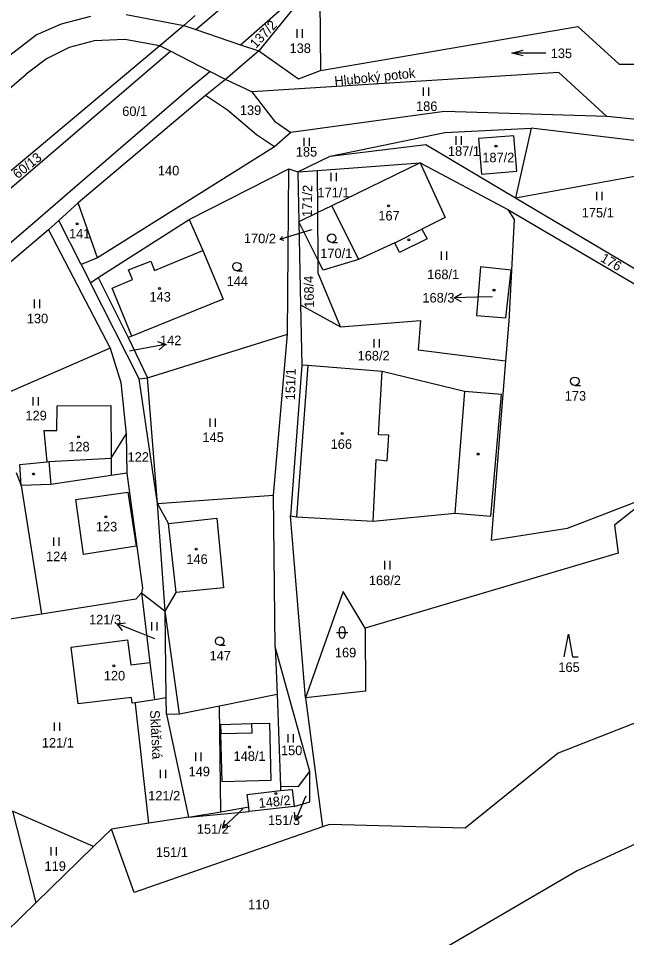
# Model space of a CAD drawing. Extents: x -670359 to -668019, y -978807 to -976674.
# Drawn here: x -669999.1 to -669891.1, y -977284.7 to -977121.4 of the extents above; entities that cross this region are included whole.
import ezdxf

# ---------------------------------------------------------------- set-up
doc = ezdxf.new("R2010")
doc.units = 0
for name, color, linetype in [('Hranice kat_území', 7, 'Continuous'), ('Hranice parcel', 7, 'Continuous'), ('Parcelní čísla', 7, 'Continuous'), ('Pop  PČ popisy', 7, 'Continuous'), ('Vnitřní kresba', 7, 'Continuous'), ('Značky budov', 7, 'Continuous'), ('Značky kultur', 7, 'Continuous')]:
    doc.layers.add(name, color=color, linetype=linetype)

msp = doc.modelspace()

# ---------------------------------------------------------------- linework, layer by layer
at = {"layer": 'Hranice kat_území'}
for points in [[(-669945.6, -977118.07), (-669945.45, -977130.61)], [(-669945.45, -977130.61), (-669899.75, -977122.83)], [(-669899.75, -977122.83), (-669892.44, -977129.5)], [(-669892.44, -977129.5), (-669889.16, -977129.48)]]:
    msp.add_lwpolyline(points, dxfattribs=at)
at = {"layer": 'Hranice parcel'}
for p, q in [((-669917.06, -977165.52), (-669917.76, -977174.17)), ((-669911.59, -977166.08), (-669917.06, -977165.52)), ((-669912.54, -977174.58), (-669911.59, -977166.08)), ((-669917.76, -977174.17), (-669912.54, -977174.58))]:
    msp.add_line(p, q, dxfattribs=at)
for points in [[(-669967.58, -977123.35), (-669935.98, -977096.52)], [(-669959.66, -977126.05), (-669945.23, -977113.35)], [(-669945.23, -977113.35), (-669956.43, -977127.16)], [(-669991.49, -977122.33), (-669986.23, -977120.98)], [(-669979.99, -977120.67), (-669969.73, -977122.61)], [(-669969.73, -977122.61), (-669967.72, -977120.86)], [(-669995.94, -977124.31), (-669991.49, -977122.33)], [(-669969.73, -977122.61), (-669974.03, -977126.23)], [(-669969.73, -977122.61), (-669967.58, -977123.35)], [(-669967.58, -977123.35), (-669959.66, -977126.05)], [(-670000.63, -977127.93), (-669995.94, -977124.31)], [(-669974.03, -977126.23), (-670006.9, -977153.84)], [(-669990.1, -977126.56), (-669994.12, -977128.57)], [(-669985.64, -977125.36), (-669990.1, -977126.56)], [(-669980.2, -977125.14), (-669985.64, -977125.36)], [(-669974.03, -977126.23), (-669980.2, -977125.14)], [(-669972.1, -977127.22), (-669974.03, -977126.23)], [(-669959.66, -977126.05), (-669956.43, -977127.16)], [(-670035.46, -977181.47), (-670011.48, -977160.92), (-669972.1, -977127.22)], [(-669965.11, -977130.8), (-669972.1, -977127.22)], [(-669956.43, -977127.16), (-669949.36, -977132.08)], [(-669994.12, -977128.57), (-669997.72, -977131.3)], [(-670104.59, -977250.52), (-670079.48, -977228.88), (-670031.98, -977188.17), (-670021.47, -977179.22), (-669995.68, -977157.04), (-669989.1, -977151.37), (-669968.95, -977134.02), (-669965.11, -977130.8)], [(-670045.65, -977172.49), (-669997.72, -977131.3)], [(-669962.32, -977132.23), (-669965.11, -977130.8)], [(-669903.15, -977131), (-669957.67, -977134.44)], [(-669949.36, -977132.08), (-669945.45, -977130.61)], [(-669894.63, -977138.78), (-669903.15, -977131)], [(-669962.32, -977132.23), (-669965.9, -977135.05)], [(-669957.67, -977134.44), (-669962.32, -977132.23)], [(-669957.67, -977134.44), (-669953.64, -977139.61)], [(-669965.9, -977135.05), (-669988.51, -977154.12)], [(-669961.97, -977137.67), (-669965.9, -977135.05)], [(-669956.83, -977142.03), (-669961.97, -977137.67)], [(-669923.42, -977137.91), (-669950.75, -977141.67)], [(-669894.63, -977138.78), (-669923.42, -977137.91)], [(-669953.64, -977139.61), (-669950.75, -977141.67)], [(-669888.79, -977139.39), (-669894.63, -977138.78)], [(-669923.4, -977141.67), (-669908.05, -977140.86)], [(-669908.05, -977140.86), (-669910.86, -977153.26)], [(-669889.81, -977143.07), (-669908.05, -977140.86)], [(-669953.62, -977144.17), (-669956.83, -977142.03)], [(-669950.75, -977141.67), (-669953.62, -977144.17)], [(-669943.77, -977145.87), (-669923.4, -977141.67)], [(-669911.11, -977142.21), (-669917.4, -977142.73)], [(-669917.4, -977142.73), (-669916.9, -977149.02)], [(-669910.61, -977148.52), (-669911.11, -977142.21)], [(-669953.62, -977144.17), (-669985.1, -977163.93)], [(-669943.77, -977145.87), (-669926.75, -977143.77)], [(-669926.75, -977143.77), (-669910.86, -977153.26)], [(-669949.51, -977148.63), (-669943.77, -977145.87)], [(-669945.99, -977148.37), (-669927.77, -977147.05)], [(-669927.77, -977147.05), (-669943.48, -977154.66)], [(-669927.77, -977147.05), (-669912.21, -977155.35)], [(-669927.77, -977147.05), (-669923.32, -977156.77)], [(-669968.82, -977157.12), (-669951.12, -977148.07)], [(-669951.36, -977177.48), (-669951.12, -977148.07)], [(-669951.12, -977148.07), (-669949.51, -977148.63)], [(-669949.51, -977148.63), (-669945.99, -977148.37)], [(-669949.51, -977148.63), (-669949.32, -977157.49)], [(-669945.92, -977155.84), (-669945.99, -977148.37)], [(-669916.9, -977149.02), (-669910.61, -977148.52)], [(-669988.51, -977154.12), (-669991.93, -977157.26)], [(-669985.1, -977163.93), (-669988.51, -977154.12)], [(-669910.86, -977153.26), (-669880.3, -977171.38)], [(-669945.92, -977155.84), (-669949.32, -977157.49)], [(-669943.48, -977154.66), (-669945.92, -977155.84)], [(-669945.87, -977164.39), (-669945.92, -977155.84)], [(-669943.48, -977154.66), (-669938.71, -977164.22)], [(-669912.21, -977155.35), (-669880.68, -977173.86)], [(-669912.21, -977155.35), (-669911.08, -977157.1)], [(-669991.93, -977157.26), (-669993.77, -977158.95)], [(-669987.97, -977165.07), (-669991.93, -977157.26)], [(-669984.94, -977167.41), (-669968.82, -977157.12)], [(-669968.82, -977157.12), (-669966.34, -977162.58)], [(-669945.87, -977164.39), (-669949.32, -977157.49)], [(-669949.32, -977157.49), (-669949, -977172.24)], [(-669923.32, -977156.77), (-669927.47, -977158.8)], [(-669911.08, -977157.1), (-669912.02, -977175.17)], [(-669993.77, -977158.95), (-670006.42, -977169.66)], [(-669993.77, -977158.95), (-669982.85, -977179.94)], [(-669927.47, -977158.8), (-669926.5, -977160.55)], [(-669926.5, -977160.55), (-669931.44, -977162.98)], [(-669966.34, -977162.58), (-669962.75, -977171.23)], [(-669932.25, -977161.22), (-669938.71, -977164.22)], [(-669931.44, -977162.98), (-669932.25, -977161.22)], [(-669985.1, -977163.93), (-669987.97, -977165.07)], [(-669938.71, -977164.22), (-669945.02, -977166.09)], [(-669987.97, -977165.07), (-669986.3, -977168.37)], [(-669945.02, -977166.09), (-669945.87, -977164.39)], [(-669941.9, -977176.15), (-669945.86, -977166.62), (-669945.87, -977164.39)], [(-669986.3, -977168.37), (-669984.94, -977167.41)], [(-669984.94, -977167.41), (-669979.64, -977178.07)], [(-669977.7, -977185.39), (-669986.3, -977168.37)], [(-669962.75, -977171.23), (-669978.99, -977177.81)], [(-669949, -977172.24), (-669948.77, -977182.97)], [(-669949, -977172.24), (-669941.9, -977176.15)], [(-669941.9, -977176.15), (-669927.7, -977175.07), (-669928.11, -977180.28), (-669912.59, -977182.2)], [(-669912.02, -977175.17), (-669912.59, -977182.2)], [(-669978.99, -977177.81), (-669979.64, -977178.07)], [(-669979.64, -977178.07), (-669976.19, -977185.22)], [(-669976.19, -977185.22), (-669951.36, -977177.48)], [(-669953.8, -977206.06), (-669951.36, -977177.48)], [(-669982.85, -977179.94), (-670002.6, -977188.53)], [(-669982.85, -977179.94), (-669980.9, -977186.05)], [(-669948.77, -977182.97), (-669950.8, -977209.75)], [(-669947.73, -977183.05), (-669948.77, -977182.97)], [(-669934.53, -977184.09), (-669947.73, -977183.05)], [(-669912.59, -977182.2), (-669915.17, -977214.1)], [(-669977.7, -977185.39), (-669976.19, -977185.22)], [(-669974.43, -977207.58), (-669977.7, -977185.39)], [(-669919.87, -977187.68), (-669934.53, -977184.09)], [(-669980.9, -977186.05), (-669979.97, -977195.23)], [(-669913.31, -977188.2), (-669919.87, -977187.68)], [(-669915.2, -977209.79), (-669913.31, -977188.2)], [(-669992.29, -977194.58), (-669992.23, -977190.19)], [(-669992.23, -977190.19), (-669982.72, -977190.13)], [(-669982.72, -977190.13), (-669982.67, -977199.48)], [(-669994.53, -977194.6), (-669992.29, -977194.58)], [(-669994, -977200.14), (-669994.53, -977194.6)], [(-669979.97, -977195.23), (-669979.85, -977202.18)], [(-669998.89, -977200.62), (-669994, -977200.14)], [(-669982.67, -977199.48), (-669982.65, -977202.6)], [(-669998.63, -977204.37), (-669998.89, -977200.62)], [(-669999.53, -977202.06), (-669998.63, -977204.37)], [(-669982.65, -977202.6), (-669993.36, -977204.18)], [(-669979.85, -977202.18), (-669982.65, -977202.6)], [(-669979.85, -977202.18), (-669977.1, -977222.62)], [(-669993.36, -977204.18), (-669998.63, -977204.37)], [(-669998.63, -977204.37), (-669994.99, -977227.2)], [(-669988.94, -977206.87), (-669979.68, -977205.54)], [(-669979.68, -977205.54), (-669978.18, -977215.12)], [(-669974.43, -977207.58), (-669953.8, -977206.06)], [(-669953.54, -977233.03), (-669953.8, -977206.06)], [(-669901.59, -977211.94), (-669886.67, -977206.18)], [(-669886.67, -977206.18), (-669893.28, -977211.41)], [(-669987.53, -977216.61), (-669988.94, -977206.87)], [(-669973.08, -977226.71), (-669974.43, -977207.58)], [(-669950.8, -977209.75), (-669949.74, -977209.91)], [(-669948.13, -977242.11), (-669950.8, -977209.75)], [(-669949.74, -977209.91), (-669936.14, -977210.71)], [(-669936.14, -977210.71), (-669921.6, -977209.27)], [(-669921.6, -977209.27), (-669915.2, -977209.79)], [(-669972.45, -977211.09), (-669963.9, -977210.16)], [(-669971.1, -977223.39), (-669972.45, -977211.09)], [(-669963.9, -977210.16), (-669962.71, -977222.54)], [(-669893.28, -977211.41), (-669892.61, -977216.37)], [(-669915.17, -977214.1), (-669901.59, -977211.94)], [(-669978.18, -977215.12), (-669987.53, -977216.61)], [(-669892.61, -977216.37), (-669937.56, -977229.74)], [(-669977.1, -977222.62), (-669977.27, -977223.41)], [(-669962.71, -977222.54), (-669971.1, -977223.39)], [(-669978.29, -977224.55), (-669994.99, -977227.2)], [(-669977.27, -977223.41), (-669978.29, -977224.55)], [(-669977.27, -977223.41), (-669975.76, -977235.81)], [(-669977.27, -977223.41), (-669973.08, -977226.71)], [(-669941.43, -977223.21), (-669948.13, -977242.11)], [(-669937.56, -977229.74), (-669941.43, -977223.21)], [(-669994.99, -977227.2), (-670002.18, -977228.33)], [(-669972.86, -977242.12), (-669973.08, -977226.71)], [(-669937.56, -977229.74), (-669937.5, -977240.93)], [(-669989.74, -977233.11), (-669979.73, -977231.81)], [(-669979.73, -977231.81), (-669979.14, -977236.24)], [(-669988.49, -977243.13), (-669989.74, -977233.11)], [(-669947.38, -977255.2), (-669953.54, -977233.03)], [(-669953.54, -977233.03), (-669953.17, -977241.42)], [(-669979.14, -977236.24), (-669975.76, -977235.81)], [(-669975.76, -977235.81), (-669974.94, -977242.47)], [(-669937.5, -977240.93), (-669948.13, -977242.11)], [(-669979.02, -977242.01), (-669988.49, -977243.13)], [(-669978.91, -977243.05), (-669979.02, -977242.01)], [(-669974.94, -977242.47), (-669978.38, -977242.97)], [(-669972.86, -977242.12), (-669974.94, -977242.47)], [(-669972.82, -977244.97), (-669972.86, -977242.12)], [(-669963.43, -977243.51), (-669953.17, -977241.42)], [(-669953.17, -977241.42), (-669952.6, -977257.8)], [(-669948.13, -977242.11), (-669945.09, -977265.04)], [(-669978.38, -977242.97), (-669978.91, -977243.05)], [(-669975.96, -977264.38), (-669978.35, -977243.14), (-669978.38, -977242.97)], [(-669970.51, -977244.96), (-669963.43, -977243.51)], [(-669963.18, -977262.32), (-669963.43, -977243.51)], [(-669879.68, -977242.68), (-669903.28, -977251.92)], [(-669972.82, -977244.97), (-669970.51, -977244.96)], [(-669972.82, -977244.97), (-669968.89, -977263.29)], [(-669903.28, -977251.92), (-669919.77, -977265.25)], [(-669949.4, -977257.86), (-669947.38, -977255.2)], [(-669947.34, -977260.59), (-669947.38, -977255.2)], [(-669958.49, -977259.24), (-669952.58, -977258.58)], [(-669952.6, -977257.8), (-669949.4, -977257.86)], [(-669952.6, -977257.8), (-669952.58, -977258.58)], [(-669952.58, -977258.58), (-669950.52, -977258.35)], [(-669950.52, -977258.35), (-669950.17, -977261.42)], [(-669958.21, -977261.47), (-669958.49, -977259.24)], [(-669950.17, -977261.42), (-669947.34, -977260.59)], [(-669873.27, -977260.54), (-669899.87, -977272.82)], [(-669963.18, -977262.32), (-669958.21, -977261.47)], [(-669958.11, -977262.31), (-669958.21, -977261.47)], [(-669950.17, -977261.42), (-669958.11, -977262.31)], [(-669985.76, -977268.51), (-670000.16, -977262.24)], [(-670000.16, -977262.24), (-669996.01, -977278.51)], [(-669968.89, -977263.29), (-669975.96, -977264.38)], [(-669968.89, -977263.29), (-669958.11, -977262.31)], [(-669968.89, -977263.29), (-669963.18, -977262.32)], [(-669982.59, -977265.41), (-669985.76, -977268.51)], [(-669975.96, -977264.38), (-669982.59, -977265.41)], [(-669978.55, -977276.66), (-669982.59, -977265.41)], [(-669945.09, -977265.04), (-669978.55, -977276.66)], [(-669943.86, -977264.62), (-669945.09, -977265.04)], [(-669919.77, -977265.25), (-669943.86, -977264.62)], [(-669985.76, -977268.51), (-669996.01, -977278.51)], [(-669899.87, -977272.82), (-669928.04, -977289.3)], [(-669996.01, -977278.51), (-670001.38, -977283.75)]]:
    msp.add_lwpolyline(points, dxfattribs=at)
at = {"layer": 'Parcelní čísla'}
for p, q in [((-669947.09, -977158.94), (-669950.79, -977160.09)), ((-669950.79, -977160.09), (-669952.7, -977160.68)), ((-669952.7, -977160.68), (-669952.19, -977160.13)), ((-669951.97, -977160.85), (-669952.7, -977160.68)), ((-669920.41, -977171.73), (-669921.73, -977171.01)), ((-669915, -977170.86), (-669917.73, -977170.92)), ((-669974.4, -977178.75), (-669972.99, -977179.25)), ((-669979.38, -977180.43), (-669976.92, -977179.98)), ((-669980.63, -977230.13), (-669981.56, -977228.95)), ((-669974.9, -977231.63), (-669977.85, -977230.44)), ((-669948.07, -977259.58), (-669948.35, -977260.24)), ((-669959.3, -977261.89), (-669959.97, -977262.51)), ((-669948.73, -977263.02), (-669949.93, -977263.91)), ((-669961.44, -977264.9), (-669962.9, -977265.23))]:
    msp.add_line(p, q, dxfattribs=at)
for points in [[(-669917.73, -977170.92), (-669921.73, -977171.01), (-669920.45, -977170.23)], [(-669976.92, -977179.98), (-669972.99, -977179.25), (-669974.13, -977180.23)], [(-669977.85, -977230.44), (-669981.56, -977228.95), (-669980.07, -977228.74)], [(-669948.35, -977260.24), (-669949.93, -977263.91), (-669950.11, -977262.42)], [(-669959.97, -977262.51), (-669962.9, -977265.23), (-669962.46, -977263.8)]]:
    msp.add_lwpolyline(points, dxfattribs=at)
at = {"layer": 'Vnitřní kresba'}
for points in [[(-669956.43, -977127.16), (-669962.32, -977132.23)], [(-669910.86, -977153.26), (-669882.82, -977148.14)], [(-669932.25, -977161.22), (-669927.47, -977158.8)], [(-669974.95, -977166.16), (-669966.34, -977162.58)], [(-669979.57, -977166.07), (-669975.61, -977164.49)], [(-669975.61, -977164.49), (-669974.95, -977166.16)], [(-669978.85, -977167.79), (-669979.57, -977166.07)], [(-669982.47, -977169.3), (-669978.85, -977167.79)], [(-669978.99, -977177.81), (-669982.47, -977169.3)], [(-669947.73, -977183.05), (-669949.74, -977209.91)], [(-669974.43, -977207.58), (-669976.19, -977185.22)], [(-669935.19, -977195.36), (-669934.53, -977184.09)], [(-669919.87, -977187.68), (-669921.6, -977209.27)], [(-669982.67, -977199.48), (-669979.97, -977195.23)], [(-669933.35, -977195.43), (-669935.19, -977195.36)], [(-669933.64, -977199.99), (-669933.35, -977195.43)], [(-669994, -977200.14), (-669993.7, -977200.11)], [(-669993.7, -977200.11), (-669982.67, -977199.48)], [(-669993.7, -977200.11), (-669993.36, -977204.18)], [(-669936.14, -977210.71), (-669935.56, -977199.76)], [(-669935.56, -977199.76), (-669933.64, -977199.99)], [(-669972.45, -977211.09), (-669974.43, -977207.58)], [(-669973.08, -977226.71), (-669971.1, -977223.39)], [(-669970.51, -977244.96), (-669973.08, -977226.71)], [(-669963.21, -977246.84), (-669957.66, -977246.68)], [(-669963.21, -977246.84), (-669963.17, -977248.43)], [(-669957.66, -977246.68), (-669954.51, -977246.59)], [(-669957.61, -977248.33), (-669957.66, -977246.68)], [(-669954.51, -977246.59), (-669954.3, -977256.78)], [(-669963.17, -977248.43), (-669957.61, -977248.33)], [(-669962.96, -977256.99), (-669963.17, -977248.43)], [(-669954.3, -977256.78), (-669962.96, -977256.99)]]:
    msp.add_lwpolyline(points, dxfattribs=at)
at = {"layer": 'Značky budov'}
for centre in [(-669914.3, -977144.06), (-669933.41, -977154.67), (-669988.67, -977157.87), (-669974.08, -977169.34), (-669914.66, -977169.67), (-669941.62, -977195.11), (-669988.47, -977195.71), (-669983.57, -977209.93), (-669967.54, -977215.69), (-669982.16, -977236.41), (-669958.06, -977250.83), (-669953.38, -977259.09)]:
    msp.add_circle(centre, 0.175, dxfattribs=at)
at = {"layer": 'Značky kultur'}
for p, q in [((-669949.68, -977123.31), (-669949.68, -977124.81)), ((-669948.68, -977124.81), (-669948.68, -977123.31)), ((-669905.47, -977127.53), (-669911.47, -977127.53)), ((-669927.25, -977133.62), (-669927.25, -977135.12)), ((-669926.25, -977135.12), (-669926.25, -977133.62)), ((-669948.42, -977142.58), (-669948.42, -977144.08)), ((-669947.42, -977144.08), (-669947.42, -977142.58)), ((-669921.44, -977142.31), (-669921.44, -977143.81)), ((-669920.44, -977143.81), (-669920.44, -977142.31)), ((-669943.65, -977148.8), (-669943.65, -977150.3)), ((-669942.65, -977150.3), (-669942.65, -977148.8)), ((-669896.45, -977152.16), (-669896.45, -977153.66)), ((-669895.45, -977153.66), (-669895.45, -977152.16)), ((-669943.47, -977161.16), (-669942.47, -977161.16)), ((-669924.03, -977162.78), (-669924.03, -977164.28)), ((-669923.03, -977164.28), (-669923.03, -977162.78)), ((-669960.31, -977166.22), (-669959.31, -977166.22)), ((-669996.33, -977171.34), (-669996.33, -977172.84)), ((-669995.33, -977172.84), (-669995.33, -977171.34)), ((-669935.97, -977178.35), (-669935.97, -977179.85)), ((-669934.97, -977179.85), (-669934.97, -977178.35)), ((-669900.31, -977186.59), (-669899.31, -977186.59)), ((-669996.55, -977188.66), (-669996.55, -977190.16)), ((-669995.55, -977190.16), (-669995.55, -977188.66)), ((-669965.14, -977192.44), (-669965.14, -977193.94)), ((-669964.14, -977193.94), (-669964.14, -977192.44)), ((-669992.89, -977213.61), (-669992.89, -977215.11)), ((-669991.89, -977215.11), (-669991.89, -977213.61)), ((-669934.09, -977217.76), (-669934.09, -977219.26)), ((-669933.09, -977219.26), (-669933.09, -977217.76)), ((-669975.49, -977228.64), (-669975.49, -977230.14)), ((-669974.49, -977230.14), (-669974.49, -977228.64)), ((-669942.64, -977230.48), (-669940.64, -977230.48)), ((-669942.14, -977229.98), (-669942.14, -977230.98)), ((-669941.14, -977229.98), (-669941.14, -977230.98)), ((-669963.38, -977232.75), (-669962.38, -977232.75)), ((-669992.78, -977246.45), (-669992.78, -977247.95)), ((-669991.78, -977247.95), (-669991.78, -977246.45)), ((-669951.26, -977248.55), (-669951.26, -977250.05)), ((-669950.26, -977250.05), (-669950.26, -977248.55)), ((-669967.65, -977251.83), (-669967.65, -977253.33)), ((-669966.65, -977253.33), (-669966.65, -977251.83)), ((-669973.93, -977254.86), (-669973.93, -977256.36)), ((-669972.93, -977256.36), (-669972.93, -977254.86)), ((-669993.37, -977268.63), (-669993.37, -977270.13)), ((-669992.37, -977270.13), (-669992.37, -977268.63))]:
    msp.add_line(p, q, dxfattribs=at)
for points in [[(-669909.47, -977128.03), (-669911.47, -977127.53), (-669909.47, -977127.03)], [(-669902.19, -977234.8), (-669901.44, -977230.8), (-669900.69, -977234.8), (-669899.69, -977234.8)]]:
    msp.add_lwpolyline(points, dxfattribs=at)
for centre, radius in [((-669914.3, -977144.06), 0.175), ((-669933.41, -977154.67), 0.175), ((-669988.67, -977157.87), 0.175), ((-669943.47, -977160.41), 0.75), ((-669929.79, -977160.72), 0.175), ((-669960.31, -977165.47), 0.75), ((-669974.08, -977169.34), 0.175), ((-669914.66, -977169.67), 0.175), ((-669900.31, -977185.84), 0.75), ((-669941.62, -977195.11), 0.175), ((-669988.47, -977195.71), 0.175), ((-669917.46, -977198.77), 0.175), ((-669996.46, -977202.32), 0.175), ((-669983.57, -977209.93), 0.175), ((-669967.54, -977215.69), 0.175), ((-669963.38, -977232), 0.75), ((-669982.16, -977236.41), 0.175), ((-669958.06, -977250.83), 0.175), ((-669953.38, -977259.09), 0.175)]:
    msp.add_circle(centre, radius, dxfattribs=at)
for centre, start, end in [((-669941.64, -977229.98), 0, 180), ((-669941.64, -977230.98), 180, 0)]:
    msp.add_arc(centre, 0.5, start, end, dxfattribs=at)

# ---------------------------------------------------------------- texts
at = {"layer": 'Parcelní čísla'}
for s, rotation, p in [('137/2', 46.8624, (-669956.95, -977126.82)), ('60/13', 38.9704, (-669999.24, -977149.96)), ('171/2', 89.2669, (-669947.01, -977156.65)), ('170/2', 359.1689, (-669959.08, -977161.27)), ('176', 329.8265, (-669895.9, -977164.44)), ('168/4', 91.043, (-669946.62, -977172.77)), ('151/1', 88.4579, (-669950.01, -977189.25)), ('148/2', 5.9314, (-669956.36, -977261.67))]:
    msp.add_text(s, height=1.7, rotation=rotation, dxfattribs=at).set_placement(p)
for s, height, p in [('138', 1.7, (-669950.97, -977127.51)), ('135', 1.7, (-669904.59, -977128.42)), ('186', 1.7, (-669928.5, -977137.82)), ('60/1', 1.7, (-669980.68, -977138.72)), ('139', 1.7, (-669959.79, -977138.53)), ('185', 1.7, (-669949.85, -977145.92)), ('187/1', 1.7, (-669922.84, -977145.8)), ('187/2', 1.7, (-669916.74, -977146.94)), ('140', 1.7, (-669974.34, -977149.26)), ('171/1', 1.7, (-669946.01, -977153.15)), ('167', 1.7, (-669935.2, -977157.27)), ('175/1', 1.7, (-669899.07, -977156.73)), ('141', 1.7, (-669990.13, -977160.47)), ('170/2', 0.1, (-669947.28, -977158.94)), ('170/1', 1.7, (-669945.51, -977163.96)), ('144', 1.7, (-669962.13, -977168.92)), ('168/1', 1.7, (-669926.53, -977167.7)), ('143', 1.7, (-669975.84, -977171.68)), ('168/3', 1.7, (-669927.37, -977171.85)), ('168/3', 0.1, (-669915, -977170.86)), ('130', 1.7, (-669997.62, -977175.54)), ('142', 1.7, (-669973.97, -977179.43)), ('142', 0.1, (-669979.38, -977180.43)), ('168/2', 1.7, (-669938.88, -977182.15)), ('173', 1.7, (-669902.1, -977189.29)), ('129', 1.7, (-669997.87, -977192.79)), ('145', 1.7, (-669966.43, -977196.64)), ('128', 1.7, (-669990.26, -977198.31)), ('166', 1.7, (-669943.67, -977197.85)), ('122', 1.7, (-669979.73, -977200.15)), ('123', 1.7, (-669985.36, -977212.53)), ('124', 1.7, (-669994.21, -977217.81)), ('146', 1.7, (-669969.29, -977218.29)), ('168/2', 1.7, (-669936.88, -977222.07)), ('121/3', 1.7, (-669986.58, -977229.04)), ('121/3', 0.1, (-669975.08, -977231.63)), ('147', 1.7, (-669965.17, -977235.45)), ('169', 1.7, (-669942.91, -977234.9)), ('165', 1.7, (-669903.23, -977237.5)), ('120', 1.7, (-669983.95, -977239.01)), ('121/1', 1.7, (-669994.96, -977250.92)), ('150', 1.7, (-669952.49, -977252.28)), ('148/1', 1.7, (-669960.91, -977253.29)), ('149', 1.7, (-669968.9, -977256.03)), ('121/2', 1.7, (-669976.07, -977260.33)), ('151/3', 0.1, (-669948.07, -977259.58)), ('151/2', 0.1, (-669959.3, -977261.89)), ('151/3', 1.7, (-669954.8, -977264.69)), ('151/2', 1.7, (-669967.43, -977266.25)), ('151/1', 1.7, (-669974.7, -977270.37)), ('119', 1.7, (-669994.48, -977272.83)), ('110', 1.7, (-669958.33, -977279.65))]:
    msp.add_text(s, height=height, dxfattribs=at).set_placement(p)
at = {"layer": 'Pop  PČ popisy'}
for s, rotation, p in [('Hluboký potok', 5.9115, (-669942.91, -977133.37)), ('Sklářská', 272.8915, (-669975.75, -977244.32))]:
    msp.add_text(s, height=1.7, rotation=rotation, dxfattribs=at).set_placement(p)

doc.saveas('drawing.dxf')
